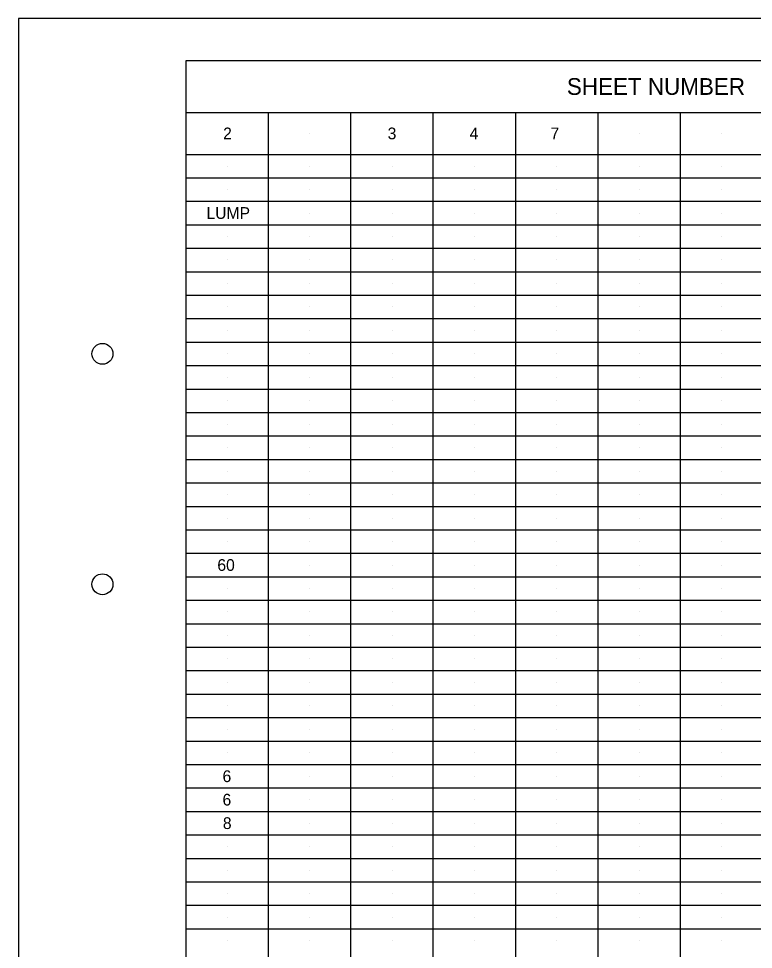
# Model space of a CAD drawing. Extents: x 1 to 35, y -2 to 20.
# Drawn here: x 1.03 to 9.79, y 8.94 to 20.04 of the extents above; entities that cross this region are included whole.
import ezdxf

# ---------------------------------------------------------------- set-up
doc = ezdxf.new("R2010")
doc.units = 0
for name, color, linetype in [('SH_Border', 7, 'Continuous'), ('SH_Cut_Line', 7, 'Continuous'), ('SH_Data', 7, 'Continuous'), ('SH_Text', 7, 'Continuous')]:
    doc.layers.add(name, color=color, linetype=linetype)

msp = doc.modelspace()

# ---------------------------------------------------------------- linework, layer by layer
at = {"layer": 'SH_Border'}
msp.add_lwpolyline([(3.031, 19.543), (34.531, 19.543), (34.531, -1.457), (3.031, -1.457)], close=True, dxfattribs=at)
for centre in [(2.031, 16.043), (2.031, 13.293)]:
    msp.add_circle(centre, 0.125, dxfattribs=at)
at = {"layer": 'SH_Cut_Line'}
msp.add_lwpolyline([(1.031, -1.957), (35.031, -1.957), (35.031, 20.043), (1.031, 20.043)], close=True, dxfattribs=at)
at = {"layer": 'SH_Data'}
for p, q in [((3.031, 18.923), (16.781, 18.923)), ((4.013, -1.457), (4.013, 18.923)), ((4.995, -1.457), (4.995, 18.923)), ((5.977, -1.457), (5.977, 18.923)), ((6.96, -1.457), (6.96, 18.923)), ((7.942, -1.457), (7.942, 18.923)), ((8.924, -1.457), (8.924, 18.923)), ((3.522, 18.673), (3.522, 18.673)), ((4.504, 18.673), (4.504, 18.673)), ((5.486, 18.673), (5.486, 18.673)), ((6.468, 18.673), (6.468, 18.673)), ((7.451, 18.673), (7.451, 18.673)), ((8.433, 18.673), (8.433, 18.673)), ((9.415, 18.673), (9.415, 18.673)), ((3.031, 18.423), (33.531, 18.423)), ((3.522, 18.283), (3.522, 18.283)), ((4.504, 18.283), (4.504, 18.283)), ((5.486, 18.283), (5.486, 18.283)), ((6.468, 18.283), (6.468, 18.283)), ((7.451, 18.283), (7.451, 18.283)), ((8.433, 18.283), (8.433, 18.283)), ((9.415, 18.283), (9.415, 18.283)), ((3.031, 18.143), (33.531, 18.143)), ((3.522, 18.003), (3.522, 18.003)), ((4.504, 18.003), (4.504, 18.003)), ((5.486, 18.003), (5.486, 18.003)), ((6.468, 18.003), (6.468, 18.003)), ((7.451, 18.003), (7.451, 18.003)), ((8.433, 18.003), (8.433, 18.003)), ((9.415, 18.003), (9.415, 18.003)), ((3.031, 17.863), (33.531, 17.863)), ((3.522, 17.723), (3.522, 17.723)), ((4.504, 17.723), (4.504, 17.723)), ((5.486, 17.723), (5.486, 17.723)), ((6.468, 17.723), (6.468, 17.723)), ((7.451, 17.723), (7.451, 17.723)), ((8.433, 17.723), (8.433, 17.723)), ((9.415, 17.723), (9.415, 17.723)), ((3.031, 17.583), (33.531, 17.583)), ((3.522, 17.443), (3.522, 17.443)), ((4.504, 17.443), (4.504, 17.443)), ((5.486, 17.443), (5.486, 17.443)), ((6.468, 17.443), (6.468, 17.443)), ((7.451, 17.443), (7.451, 17.443)), ((8.433, 17.443), (8.433, 17.443)), ((9.415, 17.443), (9.415, 17.443)), ((3.031, 17.303), (33.531, 17.303)), ((3.522, 17.163), (3.522, 17.163)), ((4.504, 17.163), (4.504, 17.163)), ((5.486, 17.163), (5.486, 17.163)), ((6.468, 17.163), (6.468, 17.163)), ((7.451, 17.163), (7.451, 17.163)), ((8.433, 17.163), (8.433, 17.163)), ((9.415, 17.163), (9.415, 17.163)), ((3.031, 17.023), (33.531, 17.023)), ((3.522, 16.883), (3.522, 16.883)), ((4.504, 16.883), (4.504, 16.883)), ((5.486, 16.883), (5.486, 16.883)), ((6.468, 16.883), (6.468, 16.883)), ((7.451, 16.883), (7.451, 16.883)), ((8.433, 16.883), (8.433, 16.883)), ((9.415, 16.883), (9.415, 16.883)), ((3.031, 16.743), (33.531, 16.743)), ((3.522, 16.603), (3.522, 16.603)), ((4.504, 16.603), (4.504, 16.603)), ((5.486, 16.603), (5.486, 16.603)), ((6.468, 16.603), (6.468, 16.603)), ((7.451, 16.603), (7.451, 16.603)), ((8.433, 16.603), (8.433, 16.603)), ((9.415, 16.603), (9.415, 16.603)), ((3.031, 16.463), (33.531, 16.463)), ((3.522, 16.323), (3.522, 16.323)), ((4.504, 16.323), (4.504, 16.323)), ((5.486, 16.323), (5.486, 16.323)), ((6.468, 16.323), (6.468, 16.323)), ((7.451, 16.323), (7.451, 16.323)), ((8.433, 16.323), (8.433, 16.323)), ((9.415, 16.323), (9.415, 16.323)), ((3.031, 16.183), (33.531, 16.183)), ((3.522, 16.043), (3.522, 16.043)), ((4.504, 16.043), (4.504, 16.043)), ((5.486, 16.043), (5.486, 16.043)), ((6.468, 16.043), (6.468, 16.043)), ((7.451, 16.043), (7.451, 16.043)), ((8.433, 16.043), (8.433, 16.043)), ((9.415, 16.043), (9.415, 16.043)), ((3.031, 15.903), (33.531, 15.903)), ((3.522, 15.763), (3.522, 15.763)), ((4.504, 15.763), (4.504, 15.763)), ((5.486, 15.763), (5.486, 15.763)), ((6.468, 15.763), (6.468, 15.763)), ((7.451, 15.763), (7.451, 15.763)), ((8.433, 15.763), (8.433, 15.763)), ((9.415, 15.763), (9.415, 15.763)), ((3.031, 15.623), (33.531, 15.623)), ((3.522, 15.483), (3.522, 15.483)), ((4.504, 15.483), (4.504, 15.483)), ((5.486, 15.483), (5.486, 15.483)), ((6.468, 15.483), (6.468, 15.483)), ((7.451, 15.483), (7.451, 15.483)), ((8.433, 15.483), (8.433, 15.483)), ((9.415, 15.483), (9.415, 15.483)), ((3.031, 15.343), (33.531, 15.343)), ((3.522, 15.203), (3.522, 15.203)), ((4.504, 15.203), (4.504, 15.203)), ((5.486, 15.203), (5.486, 15.203)), ((6.468, 15.203), (6.468, 15.203)), ((7.451, 15.203), (7.451, 15.203)), ((8.433, 15.203), (8.433, 15.203)), ((9.415, 15.203), (9.415, 15.203)), ((3.031, 15.063), (33.531, 15.063)), ((3.522, 14.923), (3.522, 14.923)), ((4.504, 14.923), (4.504, 14.923)), ((5.486, 14.923), (5.486, 14.923)), ((6.468, 14.923), (6.468, 14.923)), ((7.451, 14.923), (7.451, 14.923)), ((8.433, 14.923), (8.433, 14.923)), ((9.415, 14.923), (9.415, 14.923)), ((3.031, 14.783), (33.531, 14.783)), ((3.522, 14.643), (3.522, 14.643)), ((4.504, 14.643), (4.504, 14.643)), ((5.486, 14.643), (5.486, 14.643)), ((6.468, 14.643), (6.468, 14.643)), ((7.451, 14.643), (7.451, 14.643)), ((8.433, 14.643), (8.433, 14.643)), ((9.415, 14.643), (9.415, 14.643)), ((3.031, 14.503), (33.531, 14.503)), ((3.522, 14.363), (3.522, 14.363)), ((4.504, 14.363), (4.504, 14.363)), ((5.486, 14.363), (5.486, 14.363)), ((6.468, 14.363), (6.468, 14.363)), ((7.451, 14.363), (7.451, 14.363)), ((8.433, 14.363), (8.433, 14.363)), ((9.415, 14.363), (9.415, 14.363)), ((3.031, 14.223), (33.531, 14.223)), ((3.522, 14.083), (3.522, 14.083)), ((4.504, 14.083), (4.504, 14.083)), ((5.486, 14.083), (5.486, 14.083)), ((6.468, 14.083), (6.468, 14.083)), ((7.451, 14.083), (7.451, 14.083)), ((8.433, 14.083), (8.433, 14.083)), ((9.415, 14.083), (9.415, 14.083)), ((3.031, 13.943), (33.531, 13.943)), ((3.522, 13.803), (3.522, 13.803)), ((4.504, 13.803), (4.504, 13.803)), ((5.486, 13.803), (5.486, 13.803)), ((6.468, 13.803), (6.468, 13.803)), ((7.451, 13.803), (7.451, 13.803)), ((8.433, 13.803), (8.433, 13.803)), ((9.415, 13.803), (9.415, 13.803)), ((3.031, 13.663), (33.531, 13.663)), ((3.522, 13.523), (3.522, 13.523)), ((4.504, 13.523), (4.504, 13.523)), ((5.486, 13.523), (5.486, 13.523)), ((6.468, 13.523), (6.468, 13.523)), ((7.451, 13.523), (7.451, 13.523)), ((8.433, 13.523), (8.433, 13.523)), ((9.415, 13.523), (9.415, 13.523)), ((3.031, 13.383), (33.531, 13.383)), ((3.522, 13.243), (3.522, 13.243)), ((4.504, 13.243), (4.504, 13.243)), ((5.486, 13.243), (5.486, 13.243)), ((6.468, 13.243), (6.468, 13.243)), ((7.451, 13.243), (7.451, 13.243)), ((8.433, 13.243), (8.433, 13.243)), ((9.415, 13.243), (9.415, 13.243)), ((3.031, 13.103), (33.531, 13.103)), ((3.522, 12.963), (3.522, 12.963)), ((4.504, 12.963), (4.504, 12.963)), ((5.486, 12.963), (5.486, 12.963)), ((6.468, 12.963), (6.468, 12.963)), ((7.451, 12.963), (7.451, 12.963)), ((8.433, 12.963), (8.433, 12.963)), ((9.415, 12.963), (9.415, 12.963)), ((3.031, 12.823), (33.531, 12.823)), ((3.522, 12.683), (3.522, 12.683)), ((4.504, 12.683), (4.504, 12.683)), ((5.486, 12.683), (5.486, 12.683)), ((6.468, 12.683), (6.468, 12.683)), ((7.451, 12.683), (7.451, 12.683)), ((8.433, 12.683), (8.433, 12.683)), ((9.415, 12.683), (9.415, 12.683)), ((3.031, 12.543), (33.531, 12.543)), ((3.522, 12.403), (3.522, 12.403)), ((4.504, 12.403), (4.504, 12.403)), ((5.486, 12.403), (5.486, 12.403)), ((6.468, 12.403), (6.468, 12.403)), ((7.451, 12.403), (7.451, 12.403)), ((8.433, 12.403), (8.433, 12.403)), ((9.415, 12.403), (9.415, 12.403)), ((3.031, 12.263), (33.531, 12.263)), ((3.522, 12.123), (3.522, 12.123)), ((4.504, 12.123), (4.504, 12.123)), ((5.486, 12.123), (5.486, 12.123)), ((6.468, 12.123), (6.468, 12.123)), ((7.451, 12.123), (7.451, 12.123)), ((8.433, 12.123), (8.433, 12.123)), ((9.415, 12.123), (9.415, 12.123)), ((3.031, 11.983), (33.531, 11.983)), ((3.522, 11.843), (3.522, 11.843)), ((4.504, 11.843), (4.504, 11.843)), ((5.486, 11.843), (5.486, 11.843)), ((6.468, 11.843), (6.468, 11.843)), ((7.451, 11.843), (7.451, 11.843)), ((8.433, 11.843), (8.433, 11.843)), ((9.415, 11.843), (9.415, 11.843)), ((3.031, 11.703), (33.531, 11.703)), ((3.522, 11.563), (3.522, 11.563)), ((4.504, 11.563), (4.504, 11.563)), ((5.486, 11.563), (5.486, 11.563)), ((6.468, 11.563), (6.468, 11.563)), ((7.451, 11.563), (7.451, 11.563)), ((8.433, 11.563), (8.433, 11.563)), ((9.415, 11.563), (9.415, 11.563)), ((3.031, 11.423), (33.531, 11.423)), ((3.522, 11.283), (3.522, 11.283)), ((4.504, 11.283), (4.504, 11.283)), ((5.486, 11.283), (5.486, 11.283)), ((6.468, 11.283), (6.468, 11.283)), ((7.451, 11.283), (7.451, 11.283)), ((8.433, 11.283), (8.433, 11.283)), ((9.415, 11.283), (9.415, 11.283)), ((3.031, 11.143), (33.531, 11.143)), ((3.522, 11.003), (3.522, 11.003)), ((4.504, 11.003), (4.504, 11.003)), ((5.486, 11.003), (5.486, 11.003)), ((6.468, 11.003), (6.468, 11.003)), ((7.451, 11.003), (7.451, 11.003)), ((8.433, 11.003), (8.433, 11.003)), ((9.415, 11.003), (9.415, 11.003)), ((3.031, 10.863), (33.531, 10.863)), ((3.522, 10.723), (3.522, 10.723)), ((4.504, 10.723), (4.504, 10.723)), ((5.486, 10.723), (5.486, 10.723)), ((6.468, 10.723), (6.468, 10.723)), ((7.451, 10.723), (7.451, 10.723)), ((8.433, 10.723), (8.433, 10.723)), ((9.415, 10.723), (9.415, 10.723)), ((3.031, 10.583), (33.531, 10.583)), ((3.522, 10.443), (3.522, 10.443)), ((4.504, 10.443), (4.504, 10.443)), ((5.486, 10.443), (5.486, 10.443)), ((6.468, 10.443), (6.468, 10.443)), ((7.451, 10.443), (7.451, 10.443)), ((8.433, 10.443), (8.433, 10.443)), ((9.415, 10.443), (9.415, 10.443)), ((3.031, 10.303), (33.531, 10.303)), ((3.522, 10.163), (3.522, 10.163)), ((4.504, 10.163), (4.504, 10.163)), ((5.486, 10.163), (5.486, 10.163)), ((6.468, 10.163), (6.468, 10.163)), ((7.451, 10.163), (7.451, 10.163)), ((8.433, 10.163), (8.433, 10.163)), ((9.415, 10.163), (9.415, 10.163)), ((3.031, 10.023), (33.531, 10.023)), ((3.522, 9.883), (3.522, 9.883)), ((4.504, 9.883), (4.504, 9.883)), ((5.486, 9.883), (5.486, 9.883)), ((6.468, 9.883), (6.468, 9.883)), ((7.451, 9.883), (7.451, 9.883)), ((8.433, 9.883), (8.433, 9.883)), ((9.415, 9.883), (9.415, 9.883)), ((3.031, 9.743), (33.531, 9.743)), ((3.522, 9.603), (3.522, 9.603)), ((4.504, 9.603), (4.504, 9.603)), ((5.486, 9.603), (5.486, 9.603)), ((6.468, 9.603), (6.468, 9.603)), ((7.451, 9.603), (7.451, 9.603)), ((8.433, 9.603), (8.433, 9.603)), ((9.415, 9.603), (9.415, 9.603)), ((3.031, 9.463), (33.531, 9.463)), ((3.522, 9.323), (3.522, 9.323)), ((4.504, 9.323), (4.504, 9.323)), ((5.486, 9.323), (5.486, 9.323)), ((6.468, 9.323), (6.468, 9.323)), ((7.451, 9.323), (7.451, 9.323)), ((8.433, 9.323), (8.433, 9.323)), ((9.415, 9.323), (9.415, 9.323)), ((3.031, 9.183), (33.531, 9.183)), ((3.522, 9.043), (3.522, 9.043)), ((4.504, 9.043), (4.504, 9.043)), ((5.486, 9.043), (5.486, 9.043)), ((6.468, 9.043), (6.468, 9.043)), ((7.451, 9.043), (7.451, 9.043)), ((8.433, 9.043), (8.433, 9.043)), ((9.415, 9.043), (9.415, 9.043))]:
    msp.add_line(p, q, dxfattribs=at)

# ---------------------------------------------------------------- texts
msp.add_text('SHEET NUMBER', height=0.2, dxfattribs=at).set_placement((7.57, 19.133))
at = {"layer": 'SH_Text'}
for s, p in [('2', (3.47, 18.603)), ('3', (5.432, 18.603)), ('4', (6.41, 18.603)), ('7', (7.375, 18.603)), ('LUMP', (3.271, 17.653)), ('60', (3.401, 13.453)), ('6', (3.463, 10.933)), ('6', (3.463, 10.653)), ('8', (3.467, 10.373))]:
    msp.add_text(s, height=0.14, dxfattribs=at).set_placement(p)

doc.saveas('drawing.dxf')
